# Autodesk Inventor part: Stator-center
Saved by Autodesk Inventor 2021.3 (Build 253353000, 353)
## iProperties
Created: 2021-10
Part Number: Stator-center
Material: Generic
Document SubType Name: Modeling
Designer: Administrator
Density: 1 g/cm^3
Appearance: Default
Title: Stator-center v3
Author: Administrator
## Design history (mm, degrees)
feature "Body1"
feature "Body5"
feature "Body6"
feature "Body7"
body "Solid1"
body "Solid2"
body "Solid3"
body "Solid4"
